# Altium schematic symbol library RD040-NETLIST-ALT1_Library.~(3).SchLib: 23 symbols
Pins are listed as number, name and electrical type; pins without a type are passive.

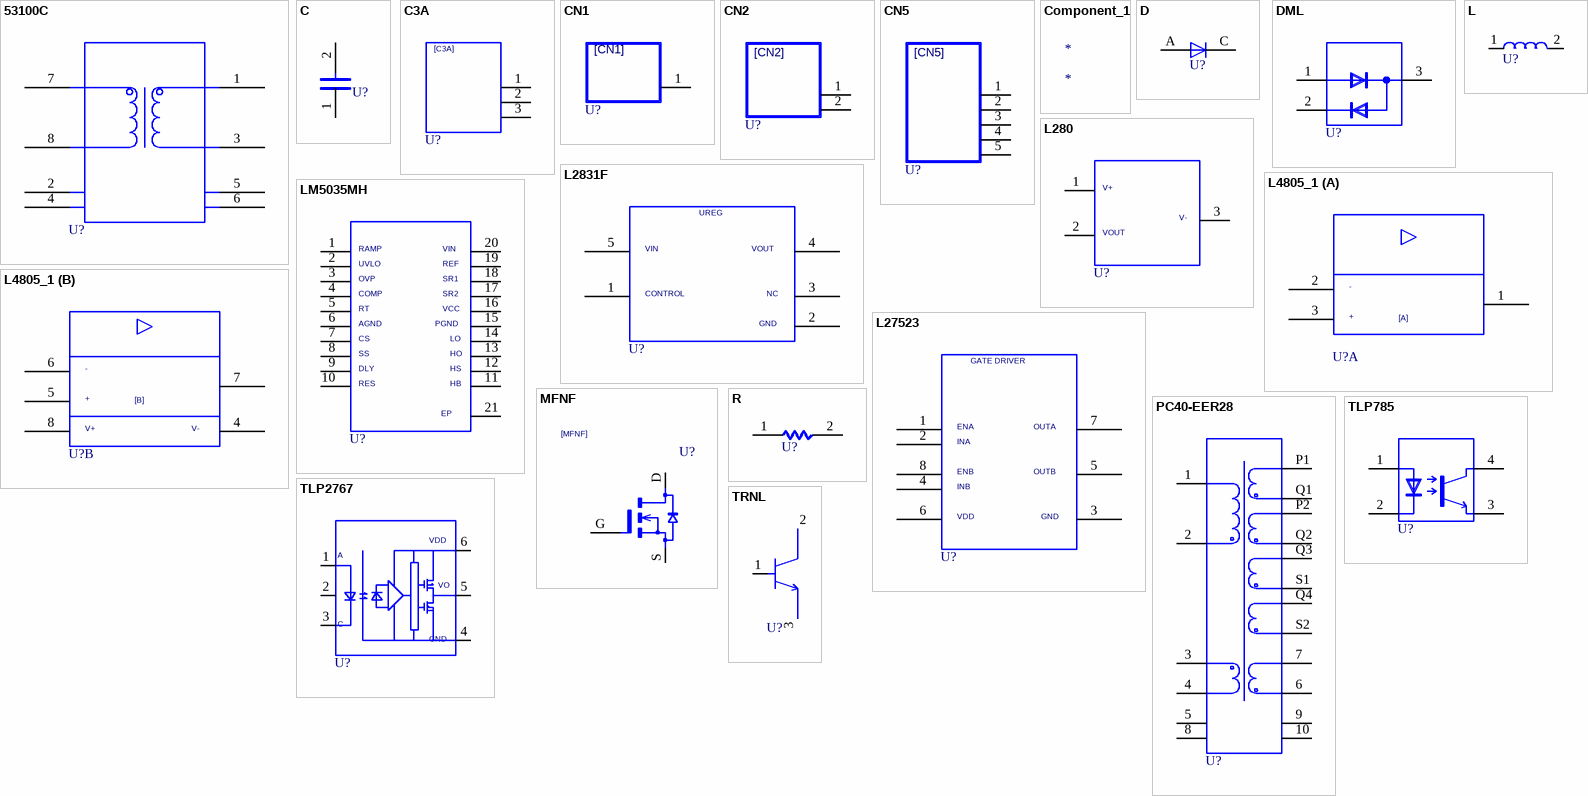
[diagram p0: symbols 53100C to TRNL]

## 53100C
designator U?  (value not drawn)
SAVEAREA0: -14581,-371,55282,35914; SAVECOUNT: 9; TIME: 14:27:07; UPDATEUSER: cae; UPDATETIME: 15:56:07; OriginalSymbolOrigin: (7620,33020); Altium-Right: 100; Altium-Bottom: 120
pins: 1, 2, 3, 4, 5, 6, 7, 8

## C
designator U?  (value not drawn)
OriginalSymbolOrigin: (2540,7620); Altium-Right: 20; Altium-Bottom: 10
pins: 1, 2

## C3A
designator U?  (value not drawn)
SAVEAREA0: -6798,-236,26764,20869; TIME: 09:53:04; UPDATEUSER: tomizawa-y; UPDATETIME: 09:53:12; SAVECOUNT: 2; OriginalSymbolOrigin: (2540,17780); Altium-Right: 50; Altium-Bottom: 60
pins: 1, 2, 3

## CN1
designator U?  (value not drawn)
OriginalSymbolOrigin: (2540,12700); Altium-Right: 50; Altium-Bottom: 40
pins: 1

## CN2
designator U?  (value not drawn)
OriginalSymbolOrigin: (2540,15240); Altium-Right: 50; Altium-Bottom: 60
pins: 1, 2

## CN5
designator U?  (value not drawn)
OriginalSymbolOrigin: (2540,22860); Altium-Right: 50; Altium-Bottom: 90
pins: 1, 2, 3, 4, 5

## Component_1
designator *

## D
designator U?  (value not drawn)
SAVEAREA0: -225,-91,12804,7836; SAVECOUNT: 3; TIME: 14:49:55; UPDATEUSER: 19870035; UPDATETIME: 14:20:16; OriginalSymbolOrigin: (5080,5080); Altium-Right: 10; Altium-Bottom: 20
pins: A, C

## DML
designator U?  (value not drawn)
SAVEAREA0: -6496,-188,29064,18281; TIME: 11:11:28; UPDATEUSER: cae; UPDATETIME: 11:19:31; SAVECOUNT: 3; OriginalSymbolOrigin: (5080,17780); Altium-Right: 50; Altium-Bottom: 60
pins: 1, 2, 3

## L
designator U?  (value not drawn)
OriginalSymbolOrigin: (2540,5080); Altium-Right: 30; Altium-Bottom: 20
pins: 1, 2

## L280
designator U?  (value not drawn)
SAVECOUNT: 18; SAVEAREA0: -9081,-242,36640,23504; TIME: 17:47:02; UPDATEUSER: cae; UPDATETIME: 15:11:54; OriginalSymbolOrigin: (5080,20320); Altium-Right: 70
pins: 1, 2, 3

## L2831F
designator U?  (value not drawn)
SAVECOUNT: 29; SAVEAREA0: -12415,-12415,55780,32568; TIME: 17:38:05; UPDATEUSER: cae; UPDATETIME: 11:39:08; OriginalSymbolOrigin: (7620,25400); Altium-Right: 110; Altium-Bottom: 90
pins: 1, 2, 3, 4, 5

## L4805_1
designator U?  (value not drawn)
SAVECOUNT: 184; SAVEAREA0: -7024,-4200,47866,32007; TIME: 22:14:29; UPDATEUSER: cae; UPDATETIME: 16:00:05; FUNCTION: OP-AMP(DUAL)_2; OriginalSymbolOrigin: (7620,25400); Altium-Right: 100; Altium-Bottom: 80; Altium-Bottom1: 90
part A pins: 1, 2, 3
part B pins: 4, 5, 6, 7, 8

## L27523
designator U?  (value not drawn)
SAVEAREA0: -10704,-787,48955,38565; SAVECOUNT: 17; TIME: 12:23:18; UPDATEUSER: cae; UPDATETIME: 08:35:05; OriginalSymbolOrigin: (7620,35560); Altium-Right: 90; Altium-Bottom: 130
pins: 1, 2, 3, 4, 5, 6, 7, 8

## LM5035MH
designator U?  (value not drawn)
TIME: 16:59:57; UPDATEUSER: cae; UPDATETIME: 13:47:07; SAVECOUNT: 6; SAVEAREA0: -25727,-431,55556,41786; OriginalSymbolOrigin: (5080,38100); Altium-Right: 80; Altium-Bottom: 140
pins: 1, 2, 3, 4, 5, 6, 7, 8, 9, 10, 11, 12, 13, 14, 15, 16, 17, 18, 19, 20, 21

## MFNF
designator U?  (value not drawn)
SAVECOUNT: 11; SAVEAREA0: -7027,-292,21786,15988; OriginalSymbolOrigin: (5080,12700); Altium-Right: 40
pins: D, G, S

## PC40-EER28
designator U?  (value not drawn)
TIME: 10:32:21; UPDATEUSER: cae; UPDATETIME: 16:55:25; SAVECOUNT: 8; SAVEAREA0: -47471,-620,69376,60068; OriginalSymbolOrigin: (5080,55880); Altium-Right: 50; Altium-Bottom: 210
pins: 1, 2, 3, 4, 5, 6, 7, 8, 9, 10, P1, P2, Q1, Q2, Q3, Q4, S1, S2

## R
designator U?  (value not drawn)
OriginalSymbolOrigin: (5080,5080); Altium-Right: 20
pins: 1, 2

## TLP785
designator U?  (value not drawn)
SAVEAREA0: -2309,-355,24620,17408; TIME: 13:47:14; UPDATEUSER: cae; SAVECOUNT: 1; OriginalSymbolOrigin: (5080,15240); Altium-Right: 50; Altium-Bottom: 60
pins: 1, 2, 3, 4

## TLP2767
designator U?  (value not drawn)
TIME: 11:37:10; UPDATEUSER: cae; UPDATETIME: 18:11:01; SAVECOUNT: 22; SAVEAREA0: -386,-6396,25843,34300; OriginalSymbolOrigin: (2540,25400); Altium-Right: 80; Altium-Bottom: 90
pins: 1, 2, 3, 4, 5, 6

## TRNL
designator U?  (value not drawn)
TIME: 09:39:04; UPDATEUSER: cae; UPDATETIME: 11:17:06; SAVECOUNT: 9; SAVEAREA0: -6161,-458,18680,15927; OriginalSymbolOrigin: (2540,17780); Altium-Right: 20; Altium-Bottom: 80
pins: 1, 2, 3

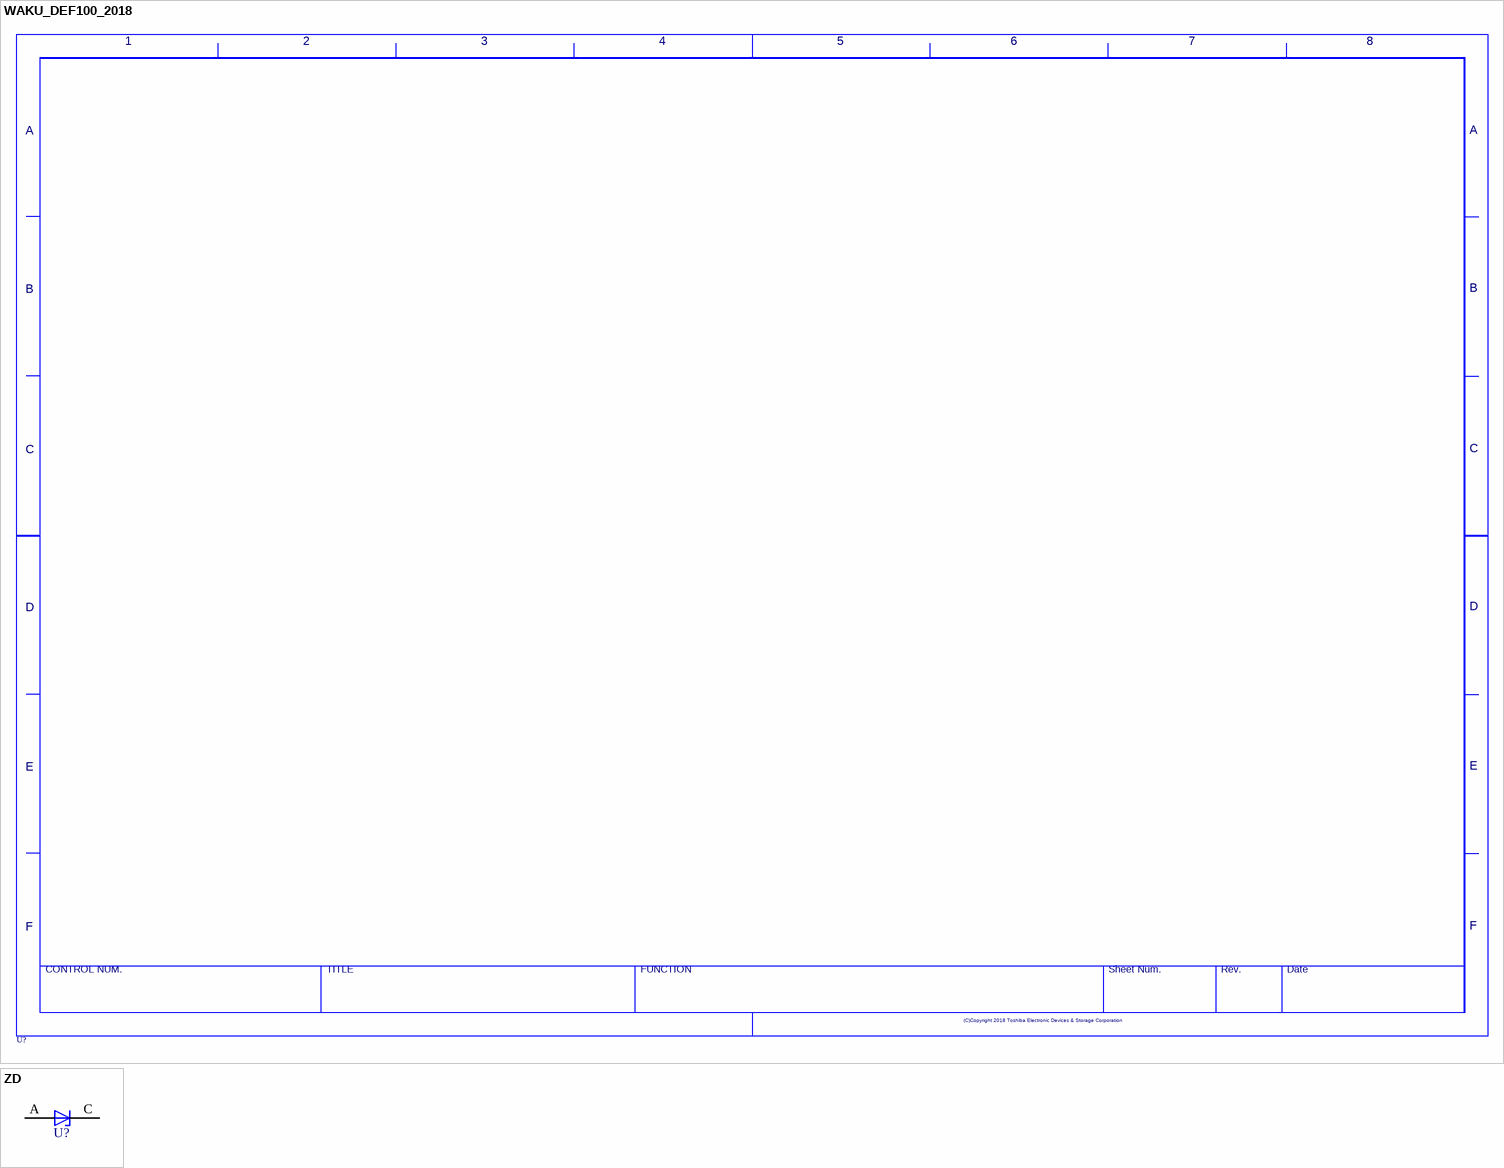
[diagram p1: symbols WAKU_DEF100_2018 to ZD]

## WAKU_DEF100_2018
designator U?  (value not drawn)
PLOTTIME: HH:MM; SAVEAREA0: -113565,-16950,524772,314592; TIME: 14:30:25; UPDATEUSER: cae; UPDATETIME: 11:15:19; SAVECOUNT: 4; OriginalSymbolOrigin: (10160,284480); Altium-Right: 1570; Altium-Bottom: 1070

## ZD
designator U?  (value not drawn)
SAVEAREA0: -4630,-153,17114,13055; TIME: 14:49:55; UPDATEUSER: fukuda-y; UPDATETIME: 08:18:42; SAVECOUNT: 6; OriginalSymbolOrigin: (5080,5080); Altium-Right: 10; Altium-Bottom: 20
pins: A, C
